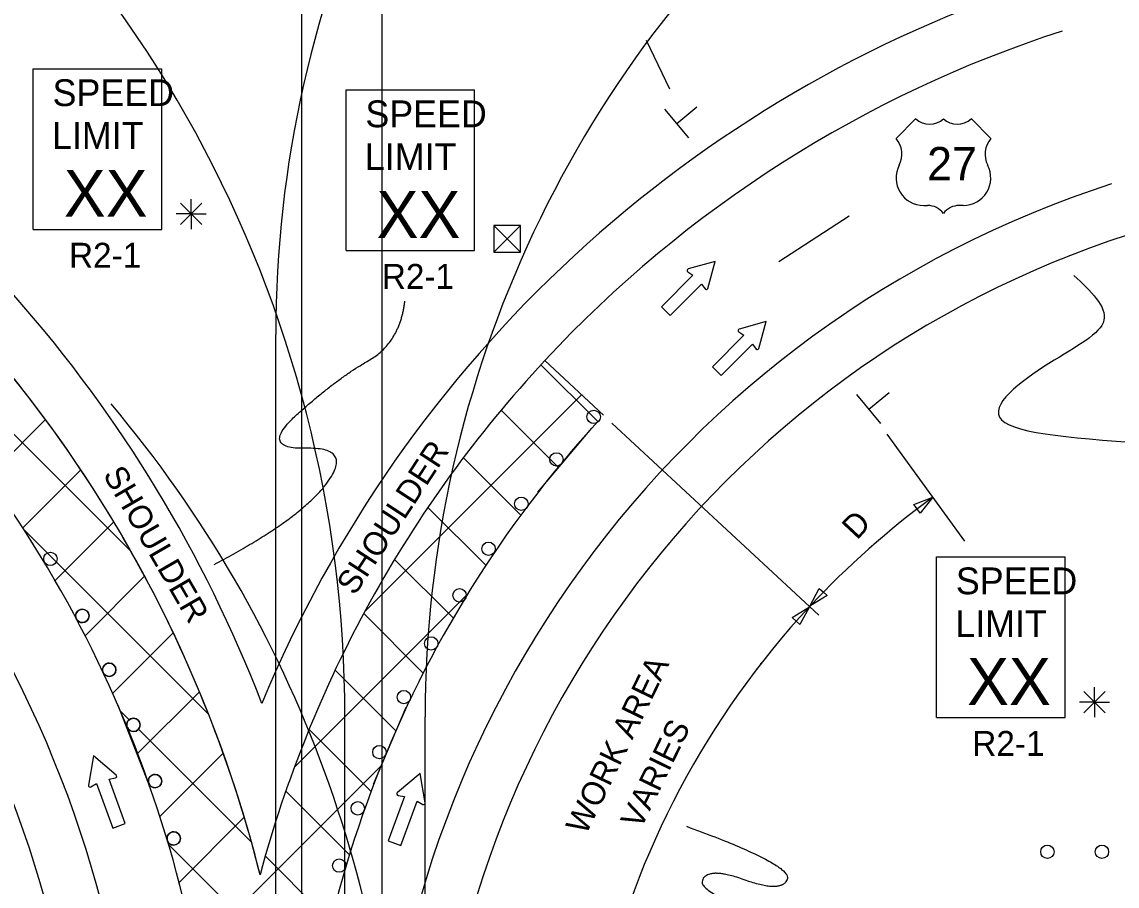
# Model space of a CAD drawing. Extents: x 16452 to 19508, y 5713 to 7079.
# Drawn here: x 16897.2 to 17224.3, y 6474.6 to 6732.8 of the extents above; entities that cross this region are included whole.
import ezdxf

# ---------------------------------------------------------------- set-up
doc = ezdxf.new("R2010")
doc.units = 0
for name, color, linetype in [('ALI_LEGAL_EX', 7, 'Continuous'), ('MT_SCRATCH_LEVEL_A', 7, 'Continuous'), ('MT_SCRATCH_LEVEL_E', 7, 'Continuous'), ('PAVT_EDGE_EX', 7, 'Continuous'), ('TRAFFIC_SIGNS_PR', 7, 'Continuous'), ('TYPICAL_EX', 7, 'Continuous'), ('TYPICAL_TEXT_DIMEN_PR', 7, 'Continuous')]:
    doc.layers.add(name, color=color, linetype=linetype)

msp = doc.modelspace()

# ---------------------------------------------------------------- linework, layer by layer
at = {"layer": 'ALI_LEGAL_EX'}
for p, q in [((16980.68, 6974.12), (16980.68, 6155.98)), ((17004.68, 6974.12), (17004.68, 6155.98)), ((16980.68, 6877.04), (16980.68, 6013.12)), ((17004.68, 6877.04), (17004.68, 6013.12)), ((16973.01, 6139.03), (16973.01, 6639.38)), ((16993.65, 6024.8), (16993.65, 6525.15)), ((17017.65, 6024.8), (17017.65, 6525.15))]:
    msp.add_line(p, q, dxfattribs=at)
for points in [[(17123.3, 6661.26), (17144.27, 6674.87)], [(17051.33, 6592.31), (17067.47, 6611.4)], [(16935.03, 6505.3), (16925.96, 6528.59)], [(17002.2, 6505.07), (17011.97, 6528.08)]]:
    msp.add_lwpolyline(points, dxfattribs=at)
for centre, radius, start, end in [((17313.01, 6639.38), 340, 129.5666, 180), ((16629.65, 6525.15), 364, 0, 57.2958), ((17357.65, 6525.15), 340, 129.5666, 180), ((16591.93, 6383.76), 364, 0, 40.1909), ((16645.75, 6383.76), 364, 0, 40.1909), ((17319.93, 6383.76), 340, 137.516, 180)]:
    msp.add_arc(centre, radius, start, end, dxfattribs=at)
at = {"layer": 'MT_SCRATCH_LEVEL_A'}
for p, q in [((17069.18, 6613.38), (17052.19, 6630.37)), ((17070.93, 6615.28), (17053.35, 6631.62)), ((16929.73, 6574.64), (16878.92, 6625.45)), ((16999.56, 6556.57), (17064.37, 6621.38)), ((17057.35, 6599.75), (17040.31, 6616.8)), ((16887.07, 6596.81), (16904.25, 6613.99)), ((17046.21, 6585.44), (17029.06, 6602.6)), ((16897.41, 6581.69), (16914.74, 6599.02)), ((17035.76, 6570.44), (17018.45, 6587.74)), ((16907.08, 6565.91), (16924.61, 6583.44)), ((16952.92, 6525.99), (16897.76, 6581.15)), ((17026.03, 6554.71), (17008.52, 6572.22)), ((16916.05, 6549.42), (16933.83, 6567.2)), ((16978.56, 6510.11), (17030.3, 6561.85)), ((17017.05, 6538.24), (16999.27, 6556.02)), ((16924.29, 6532.2), (16942.38, 6550.29)), ((17008.85, 6520.98), (16990.74, 6539.09)), ((16931.75, 6514.21), (16950.22, 6532.68)), ((16929.2, 6524.26), (16926.64, 6526.82)), ((16965.75, 6487.71), (16932.02, 6521.44)), ((17001.48, 6502.89), (16982.96, 6521.41)), ((16938.39, 6495.39), (16957.31, 6514.31)), ((16953.81, 6459.9), (17004.45, 6510.55)), ((16995.01, 6483.9), (16975.99, 6502.93)), ((16944.13, 6475.68), (16963.6, 6495.15)), ((16968.1, 6459.9), (16940.97, 6487.03)), ((16989.56, 6463.9), (16969.88, 6483.58))]:
    msp.add_line(p, q, dxfattribs=at)
for points in [[(17070.93, 6615.28), (17053.35, 6631.62), (17053.35, 6631.62)], [(16968.33, 6477.95), (16968.33, 6477.95), (16968.33, 6477.95)], [(16968.33, 6477.95), (16968.33, 6477.95)]]:
    msp.add_lwpolyline(points, dxfattribs=at)
for centre, radius, start, end in [((16591.93, 6383.76), 388, 28.2673, 40.102), ((17319.93, 6383.76), 364, 137.0843, 151.1372), ((16591.93, 6383.76), 388, 14.0483, 28.2673), ((16591.93, 6383.76), 388, 14.0483, 28.2673), ((16591.93, 6383.76), 388, 14.0483, 28.2673), ((16915.23, 6555.33), 2, 90, 205.9785), ((16915.23, 6555.33), 2, 270, 90), ((17319.93, 6383.76), 364, 151.1372, 165.0045), ((17319.93, 6383.76), 364, 151.1372, 165.0044), ((17319.93, 6383.76), 364, 151.1372, 165.0044), ((16915.23, 6555.33), 2, 209.93, 270), ((16923.27, 6539.23), 2, 90, 203.3612), ((16923.27, 6539.23), 2, 270, 90), ((16923.27, 6539.23), 2, 206.9117, 270), ((16930.51, 6522.75), 2, 90, 200.7992), ((16930.51, 6522.75), 2, 270, 90), ((16930.51, 6522.75), 2, 203.838, 270), ((16936.94, 6505.94), 2, 90, 198.3282), ((16936.94, 6505.94), 2, 270, 90), ((16936.94, 6505.94), 2, 200.6735, 270), ((16942.52, 6488.83), 2, 90, 196.0905), ((16942.52, 6488.83), 2, 197.2755, 270), ((16942.52, 6488.83), 2, 270, 90), ((17319.93, 6383.76), 364, 165.00447777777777, 165.0044972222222), ((16591.93, 6383.76), 388, 14.048225, 14.048227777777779), ((17319.93, 6383.76), 364, 165.0044, 165.0045)]:
    msp.add_arc(centre, radius, start, end, dxfattribs=at)
at = {"layer": 'MT_SCRATCH_LEVEL_E'}
for p, q in [((17096.08, 6658.17), (17097.56, 6657.14)), ((17104.24, 6661.23), (17096.22, 6659)), ((17102.07, 6653.17), (17104.24, 6661.23)), ((17097.56, 6657.14), (17088.21, 6647.74)), ((17090.86, 6645.1), (17100.21, 6654.5)), ((17100.21, 6654.5), (17101.25, 6653.03)), ((17088.21, 6647.74), (17090.86, 6645.1)), ((17119.47, 6643.28), (17111.45, 6641.04)), ((17117.3, 6635.22), (17119.47, 6643.28)), ((17112.79, 6639.19), (17103.44, 6629.79)), ((17111.31, 6640.22), (17112.79, 6639.19)), ((17106.09, 6627.15), (17115.44, 6636.55)), ((17115.44, 6636.55), (17116.48, 6635.07)), ((17103.44, 6629.79), (17106.09, 6627.15))]:
    msp.add_line(p, q, dxfattribs=at)
for centre, start, end in [((17096.35, 6658.55), 105.5821, 235.121), ((17101.62, 6653.3), 215.1934, 344.9303), ((17111.58, 6640.6), 105.5821, 235.121), ((17116.85, 6635.35), 215.1934, 344.9303)]:
    msp.add_arc(centre, 0.463, start, end, dxfattribs=at)
at = {"layer": 'PAVT_EDGE_EX'}
for centre, radius, start, end in [((17319.93, 6383.76), 380, 107.923, 157.5011), ((16591.93, 6383.76), 404, 21.0961, 61.4862), ((17319.93, 6383.76), 364, 107.923, 137.0843), ((16591.93, 6383.76), 388, 14.0482, 61.4862), ((17319.93, 6383.76), 316, 107.923, 180), ((16591.93, 6383.76), 340, 0, 61.4862), ((16591.93, 6383.76), 324, 0, 61.4862), ((17319.93, 6383.76), 300, 107.923, 180)]:
    msp.add_arc(centre, radius, start, end, dxfattribs=at)
at = {"layer": 'TRAFFIC_SIGNS_PR'}
for p, q in [((16900.57, 6718.83), (16938.97, 6718.83)), ((16900.57, 6670.83), (16900.57, 6718.83)), ((16938.97, 6670.83), (16938.97, 6718.83)), ((16994.01, 6712.51), (17032.41, 6712.51)), ((16994.01, 6664.51), (16994.01, 6712.51)), ((17032.41, 6664.51), (17032.41, 6712.51)), ((16900.57, 6670.83), (16938.97, 6670.83)), ((16994.01, 6664.51), (17032.41, 6664.51)), ((17170.41, 6572.94), (17208.81, 6572.94)), ((17170.41, 6524.94), (17170.41, 6572.94)), ((17208.81, 6524.94), (17208.81, 6572.94)), ((17170.41, 6524.94), (17208.81, 6524.94))]:
    msp.add_line(p, q, dxfattribs=at)
for centre in [(17067.98, 6614.81), (17056.86, 6602.11), (17046.37, 6588.83), (17036.58, 6575.39), (16905.68, 6572.37), (17027.91, 6561.48), (16915.23, 6555.33), (17019.45, 6547.1), (16923.27, 6539.23), (17011.28, 6531.07), (16930.51, 6522.75), (17003.96, 6514.62), (16936.94, 6505.94), (16997.51, 6497.82), (16942.52, 6488.83), (17203.52, 6484.84), (17219.82, 6484.84), (16991.96, 6480.7)]:
    msp.add_circle(centre, 2, dxfattribs=at)
at = {"layer": 'TYPICAL_EX'}
for p, q in [((17158.32, 6698.03), (17164.22, 6703.93)), ((17186.62, 6698.03), (17180.72, 6703.93)), ((17166.57, 6677.97), (17167.75, 6677.97)), ((17178.37, 6677.97), (17177.19, 6677.97))]:
    msp.add_line(p, q, dxfattribs=at)
for centre, radius, start, end in [((17168.34, 6708.22), 5.96, 226.1404, 313.8596), ((17176.6, 6708.22), 5.96, 226.1404, 313.8596), ((17152.73, 6693.31), 7.31, 333.0977, 40.1936), ((17192.21, 6693.31), 7.31, 139.8064, 206.9023), ((17166.58, 6686.22), 8.24, 152.6698, 269.9013), ((17178.36, 6686.22), 8.24, 270.0987, 27.3302), ((17167.76, 6672.07), 5.91, 37.1038, 90.1385), ((17177.18, 6672.07), 5.91, 89.8615, 142.8962)]:
    msp.add_arc(centre, radius, start, end, dxfattribs=at)
at = {"layer": 'TYPICAL_TEXT_DIMEN_PR'}
for p, q in [((17090.69, 6712.76), (17083.75, 6727.28)), ((17092.79, 6702.48), (17098.78, 6707.45)), ((17096.38, 6698.15), (17089.19, 6706.8)), ((16944.57, 6678.63), (16950.95, 6672.25)), ((16950.95, 6678.63), (16944.57, 6672.25)), ((16947.76, 6675.44), (16947.76, 6679.9)), ((16947.76, 6675.44), (16943.23, 6675.44)), ((16947.76, 6675.44), (16950.95, 6675.44)), ((16947.76, 6675.44), (16952.24, 6675.44)), ((16947.76, 6675.44), (16947.76, 6670.94)), ((17038.16, 6663.99), (17046.16, 6671.99)), ((17038.17, 6671.99), (17046.16, 6663.99)), ((17150.22, 6617.15), (17156.21, 6622.12)), ((17153.81, 6612.82), (17146.62, 6621.48)), ((17135.22, 6555.5), (17073.41, 6612.97)), ((17178.86, 6577.69), (17155.62, 6609.65)), ((17163.67, 6588.61), (17169.34, 6590.78)), ((17169.34, 6590.78), (17165.52, 6586.07)), ((17164.6, 6587.34), (17163.67, 6588.61)), ((17165.52, 6586.07), (17164.6, 6587.34)), ((17132.55, 6558.19), (17135.39, 6563.55)), ((17135.39, 6563.55), (17136.54, 6562.48)), ((17137.69, 6561.41), (17132.55, 6558.19)), ((17136.54, 6562.48), (17137.69, 6561.41)), ((17127.31, 6554.86), (17132.45, 6558.08)), ((17132.45, 6558.08), (17129.61, 6552.72)), ((17128.46, 6553.79), (17127.31, 6554.86)), ((17129.61, 6552.72), (17128.46, 6553.79)), ((17217.6, 6529.55), (17217.6, 6534.01)), ((17214.41, 6532.74), (17220.79, 6526.36)), ((17220.79, 6532.74), (17214.41, 6526.36)), ((17217.6, 6529.55), (17213.07, 6529.55)), ((17217.6, 6529.55), (17220.79, 6529.55)), ((17217.6, 6529.55), (17222.08, 6529.55)), ((17217.6, 6529.55), (17217.6, 6525.05)), ((16918.54, 6513.5), (16917.06, 6504.75)), ((16925.34, 6507.76), (16918.54, 6513.5)), ((17016.14, 6508.27), (17009.36, 6502.54)), ((17017.63, 6499.5), (17016.14, 6508.27)), ((16917.79, 6504.24), (16919.46, 6505.2)), ((16919.46, 6505.2), (16924.29, 6491.91)), ((16923.21, 6506.56), (16925.11, 6506.9)), ((16928.04, 6493.27), (16923.21, 6506.56)), ((17011.49, 6501.34), (17006.61, 6488.06)), ((17009.59, 6501.68), (17011.49, 6501.34)), ((17010.35, 6486.69), (17015.23, 6499.96)), ((17015.23, 6499.96), (17016.9, 6498.99)), ((16924.29, 6491.91), (16928.04, 6493.27)), ((17006.61, 6488.06), (17010.35, 6486.69))]:
    msp.add_line(p, q, dxfattribs=at)
msp.add_lwpolyline([(17038.17, 6671.99), (17038.16, 6663.99), (17046.16, 6663.99), (17046.16, 6671.99)], close=True, dxfattribs=at)
for centre, radius, start, end in [((17319.93, 6383.76), 256, 126.0328, 137.0506), ((17319.93, 6383.76), 256, 137.0843, 167.0592), ((17319.93, 6383.76), 256, 141.9959, 142.711), ((16925.01, 6507.38), 0.494, 280.0211, 49.758), ((16917.55, 6504.67), 0.494, 170.4097, 299.9487), ((17009.69, 6502.16), 0.494, 130.2465, 259.7854), ((17017.14, 6499.43), 0.494, 239.8578, 9.5947)]:
    msp.add_arc(centre, radius, start, end, dxfattribs=at)
for points, degree in [([(17211.47, 6657.05), (17216.36, 6652.47), (17226.42, 6643.06), (17205.46, 6632.61), (17175.74, 6610.94), (17212.37, 6608.34), (17237.36, 6606.57)], 3), ([(16954.6, 6570.72), (16980.15, 6584.14), (16996.34, 6605.78), (16967.69, 6605.06), (16991.36, 6626.3), (17010.05, 6636.91), (17011.6, 6649.4)], 2), ([(17095.73, 6492.44), (17127.37, 6480.93), (17124.25, 6472.36), (17101.95, 6480.48), (17098.84, 6471.91), (17137.06, 6458)], 2)]:
    msp.add_open_spline(points, degree=degree, dxfattribs=at)

# ---------------------------------------------------------------- texts
at = {"layer": 'TRAFFIC_SIGNS_PR'}
for s, height, p in [('SPEED', 8, (16906.34, 6707.69)), ('SPEED', 8, (16999.78, 6701.37)), ('LIMIT', 8, (16906.18, 6694.89)), ('LIMIT', 8, (16999.62, 6688.57)), ('XX', 14.031, (16909.69, 6674.59)), ('XX', 14.031, (17003.13, 6668.27)), ('R2-1', 7.44, (16911.25, 6659.39)), ('R2-1', 7.44, (17004.69, 6653.07)), ('SPEED', 8, (17176.18, 6561.8)), ('LIMIT', 8, (17176.02, 6549)), ('XX', 14.031, (17179.53, 6528.69)), ('R2-1', 7.44, (17181.09, 6513.5))]:
    msp.add_text(s, height=height, dxfattribs=at).set_placement(p)
at = {"layer": 'TYPICAL_EX'}
msp.add_text('27', height=10, dxfattribs=at).set_placement((17167.58, 6685.46))
at = {"layer": 'TYPICAL_TEXT_DIMEN_PR'}
for s, rotation, p in [('SHOULDER', 56.8597, (16996.61, 6561.15)), ('SHOULDER', 300.0663, (16921.25, 6597.55)), ('D', 46.9245, (17146.62, 6577.79)), ('WORK AREA', 64.0878, (17065.65, 6489.58)), ('VARIES', 64.0878, (17082.01, 6491.23))]:
    msp.add_text(s, height=7, rotation=rotation, dxfattribs=at).set_placement(p)

doc.saveas('drawing.dxf')
